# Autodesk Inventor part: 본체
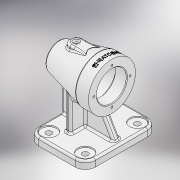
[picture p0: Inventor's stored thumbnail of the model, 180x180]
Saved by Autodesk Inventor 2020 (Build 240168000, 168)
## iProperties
Created: 2024-12
Part Number: 본체
Material: 알루미늄 6061
Document SubType Name: Modeling
Designer: 1강의실14
Density: 2.7 g/cm^3
Appearance: 알루미늄 - 평지
Mass: 737.405 g
Surface Area: 681.544 cm^2
Volume: 273.113 cm^3
Author: 1강의실14
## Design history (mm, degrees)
sketch "스케치1"
  geometry: L1 (-42, 37)-(42, 37); L2 (42, 37)-(42, 0); L3 (42, 0)-(-42, 0); L4 (-42, 0)-(-42, 37); L5 (-42, 21)-(22, 37); L6 (22, 37)-(42, 37); L7 (-42, 21)-(-42, 0); L8 (42, 37)-(42, 0); 1 further point
  constraints: 16 end point, 3 equal length, 2 perpendicular, 2 point on line, 1 horizontal, 1 midpoint, 1 vertical
  dimensions: "d0" = 84 distance of L3.end L2.end; "d2" = 42 distance from line of point (0, 0) L4; "d3" = 20 distance of L1.end L5.end; "d5" = 74 diameter of L1 L3; "d6" = 42 diameter of L5.start L3
revolve "회전1" sketch "스케치1" stored, may be unused: angle "d7" = 90 deg
sketch "스케치2"
  geometry: L1 (-42, 21)-(22, 37) reference; L2 (22, 37)-(42, 37) reference; L3 (-42, -21)-(-42, 21) reference; L4 (-42, 0)-(42, 0); L5 (-34, 0)-(-34, 15.5); L6 (-34, 15.5)-(-31, 15.5); L7 (-31, 15.5)-(-31, 17.5); L8 (-31, 17.5)-(-21, 17.5); L9 (-21, 17.5)-(-21, 21.096); L10 (24, 32.346)-(24, 23.5); L11 (24, 23.5)-(42, 23.5); L12 (24, 32.346)-(-21, 21.096); L13 (42, -37)-(42, 37) reference; L14 (42, 23.5)-(42, 0); 1 further point
  constraints: 20 end point, 5 perpendicular, 2 midpoint, 2 point on line, 1 collinear, 1 horizontal, 1 parallel, 1 vertical
  dimensions: "d11" = 5 distance between parallel lines of L1 L12; "d14" = 3 distance of L5.end L6.end; "d17" = 45 horizontal distance of L10.start L9.end; "d18" = 18 distance of L10.end L11.end; "d19" = 47 diameter of L11 L4; "d20" = 10 distance of L7.end L8.end; "d21" = 35 diameter of L8 L4; "d22" = 31 diameter of L6 L4
revolve "회전2" sketch "스케치2" stored, may be unused: angle "d23" = 90 deg
node "작업 평면1"
sketch "스케치3"
  geometry: L1 (32, -57)-(-57, -57); L2 (-57, -57)-(-57, 57); L3 (-57, 57)-(32, 57); L4 (32, 57)-(32, -57); L5 (-42, 37)-(-42, -37) reference; 1 further point
  constraints: 8 end point, 2 parallel, 1 horizontal, 1 perpendicular
  dimensions: "d25" = 89 distance of L2.end L3.end; "d26" = 114 distance of L1.end L2.end; "d27" = 15 distance between parallel lines of L2 L5; "d28" = 57 distance from line of point (0, 0) L1
extrude "돌출1" join sketch "스케치3" distance "d29" = 12; taper "d30" = 0 deg
sketch "스케치5"
  geometry: L1 (-3, -28)-(5, -28); L2 (5, -28)-(5, 28); L3 (5, 28)-(-3, 28); L4 (-3, 28)-(-3, -28); L5 (-32, 57)-(-32, -57) reference; 1 further point
  constraints: 8 end point, 2 parallel, 1 horizontal, 1 perpendicular
  dimensions: "d33" = 28 distance from line of point (0, 0) L1; "d34" = 56 distance of L1.end L2.end; "d36" = 8 distance between parallel lines of L2 L4; "d53" = 29 distance between parallel lines of L4 L5
extrude "돌출2" join sketch "스케치5" stored distance "d37" = 12; taper "d38" = 0 deg
sketch "스케치6"
  geometry: L1 (-42, -21)-(22, -37) reference; L2 (-32, -82)-(-32, -70) reference; L3 (57, -70)-(-32, -70) reference; L4 (-32, -23.5)-(-32, -70); L5 (30.947, -37)-(50, -70); L6 (57, -82)-(57, -70) reference; L7 (22, -37)-(42, -37) reference; 1 further point
  constraints: 4 end point, 3 point on line, 1 vertical
  dimensions: "d39" = 7 distance from line of L6 L5.end; "d40" = 60 deg angle of L3 L5
feature "리브1" dims "d41" = 1, "d42" = 10, "d43" = 0, "d44" = 0, "d45" = 1, "d46" = 1
feature "리브2" dims "d47" = 1, "d48" = 10, "d49" = 0, "d50" = 0, "d51" = 1, "d52" = 1
sketch "스케치7"
  geometry: L1 (-32, 57)-(-32, -57) reference; C1 r 12 at (-16, -41); 2 further points
  constraints: 1 centre point, 1 coincident
  dimensions: "d54" = 16 distance from line of point (-16, -41) L1; "d55" = 41 vertical distance of point (0, 0) point (-16, -41); "d56" = 24 diameter of C1
extrude "돌출3" cut sketch "스케치7" distance "d57" = 2; taper "d58" = 0 deg
sketch "스케치8"
  geometry: 1 further point
sketch "스케치9"
  geometry: C1 r 12 at (0, 0) reference; 2 further points
  constraints: 1 coincident
hole "구멍1" sketch "스케치9" at (0, 0) diameter "d59" = 9; stored, may be unused: countersink angle "d63" = 90 deg, drill point angle "d65" = 118 deg; dims "d60" = 6, "d61" = 4, "d62" = 2, "d64" = 8
sketch "스케치10" dims "d72" = 57
  geometry: 3 further points
  constraints: 2 vertical alignment, 1 coincident, 2 other
hole "구멍2" sketch "스케치10" at (0, 28.5) diameter "d73" = 3.242; stored, may be unused: countersink angle "d77" = 90 deg, drill point angle "d79" = 120 deg; dims "d74" = 8, "d75" = 4, "d76" = 2, "d78" = 10
node "작업 평면2"
sketch "스케치11"
  geometry: L1 (-42, 37)-(-42, -37) reference; L2 (14, -10)-(-11.736, -10); L3 (-5, -5)-(-5, -28) reference; L4 (14, 10)-(-11.736, 10); L5 (-22, 37)-(-22, -37) reference; L6 (-24, -23.5)-(-24, 23.5) reference; L7 (42, 21)-(42, -21) reference; L8 (32, 5)-(3, 5) reference; L9 (3, 5)-(3, 28) reference; L10 (3, 28)-(-5, 28) reference; L11 (-5, 28)-(-5, 5) reference; L12 (-5, 5)-(-22, 5) reference; L13 (-22, -5)-(-22, 5) reference; L14 (-22, -5)-(-5, -5) reference; L15 (-5, -5)-(-5, -28) reference; L16 (-5, -28)-(3, -28) reference; L17 (3, -28)-(3, -5) reference; L18 (3, -5)-(32, -5) reference; L19 (32, -5)-(32, 5) reference; L20 (-11.736, 10)-(-11.736, -10); A1 r 10 centre (14, 0) between (14, -10) and (14, 10); 3 further points
  constraints: 6 end point, 2 point on circle, 1 centre point, 1 horizontal, 1 perpendicular, 1 vertical
  dimensions: "d84" = 20 diameter of A1; "d85" = 56 distance from line of L1 A1.centre; "d88" = 10 distance from line of point (0, 0) L2; "d89" = 10 distance from line of L4 point (0, 0); "d96" = 19 distance from line of L2.start L3; "d115" = 11.7358 distance from line of L20 point (0, 0)
extrude "돌출6" join sketch "스케치11" stored distance "d131" = 0; taper "d132" = 0 deg
node "작업 평면3"
fillet "모깎기1" dims "d116" = 5
fillet "모깎기2" dims "d117" = 0.3
fillet "모깎기3" dims "d118" = 3
chamfer "모따기1" distance "d119" = 1; stored, may be unused: second distance "d120" = 2, angle "d121" = 45 deg
fillet "모깎기4" dims "d122" = 3
chamfer "모따기2" distance "d123" = 1; stored, may be unused: second distance "d124" = 2, angle "d125" = 45 deg
sketch "스케치15"
  geometry: L1 (-10, 37)-(-10, -37) reference; 2 further points
  constraints: 1 horizontal alignment, 1 other
  dimensions: "d111" = 9 distance from line of L1 point (-1, 0)
feature "엠보싱1" sketch "스케치15" dims "d11" = 5, "d14" = 3, "d17" = 45, "d18" = 18, "d19" = 47, "d20" = 10, "d21" = 35, "d22" = 31, "d112" = 0.5, "d113" = 0
fillet "모깎기5" dims "d126" = 3
fillet "모깎기6" dims "d127" = 3
fillet "모깎기7" dims "d128" = 16
fillet "모깎기8" dims "d129" = 3
sketch "스케치16"
  geometry: C1 r 5 at (-14, 0); A1 r 10 centre (-14, 0) between (-14, 10) and (-14, -10) reference; 1 further point
  constraints: 1 centre point, 1 coincident
  dimensions: "d133" = 10 diameter of C1
extrude "돌출7" cut sketch "스케치16" distance "d134" = 4; taper "d135" = 0 deg
sketch "스케치17"
  geometry: C1 r 5 at (0, 0) reference; 2 further points
  constraints: 1 coincident
hole "구멍4" sketch "스케치17" at (0, 0) diameter "d136" = 5.1881; stored, may be unused: countersink angle "d140" = 90 deg, drill point angle "d142" = 120 deg; dims "d137" = 14.5, "d138" = 4, "d139" = 2, "d141" = 16
fillet "모깎기10" dims "d143" = 3
fillet "모깎기11" dims "d144" = 3
fillet "모깎기12" dims "d145" = 3
fillet "모깎기13" dims "d146" = 3
node "솔리드1"
pattern_linear "직사각형 패턴1" dims "d68" = 82, "d71" = 57
pattern_circular "원형 패턴1" dims angle "d81" = 360 deg
node "투영된 루프3"
feature "A9D066F2-1C7D-4E18-AEED-F7BC21143FA4" dims "d59" = 9, "d60" = 6, "d61" = 4, "d62" = 2, "d63" = 90 deg, "d64" = 8, "d65" = 118 deg
other parameters: "d24" = -82, "d83" = -115
